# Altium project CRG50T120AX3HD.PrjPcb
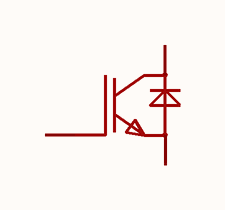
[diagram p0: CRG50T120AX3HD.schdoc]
1 sheet, 1 parts. Net scope: global (net labels, ports and power ports of the same name join across sheets).

## Sheet CRG50T120AX3HD.schdoc
size 127 x 101 mm

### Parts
Q?  crg50t120ax3hd  [TO-247-3_L15.9-W5.1-P5.44-L]  (value not drawn)

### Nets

Not connected (* = marked no-connect by the designer): Q? 1(G) 2(C) 3(E)

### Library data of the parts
Q? = crg50t120ax3hd: IGBT类型:-;耗散功率(Pd):682W;集射极击穿电压(Vces):1.2kV;集电极电流(Ic):50A;; Manufacturer: CRMICRO(华润微); AddInBom: yes; ModelId: 07f4db851a8c48cfb1c430cb719de897; ModelName: TO-247_3PIN-L15.9-W5.1-H25.0-P5.44-L; ModelTransform: 625.983,200.82637,0,0,0,0,0,5.905,-196.85; Pd - Power Dissipation: 682W; Collector-Emitter Breakdown Voltage (Vces): 1.2kV; Current - Collector(Ic): 50A; Current - Collector Pulsed (Icm): 200A; Collector Cut-Off Current (Ices): 1mA; Vce Saturation(VCE(sat)): 1.92V; Gate-Emitter Threshold Voltage (Vge(th)@Ic): 5.7V; Gate Charge(Qg): 253nC@15V; Input Capacitance(Cies): 7.852nF; Output Capacitance(Coes): 225pF; Reverse Transfer Capacitance (Cres): 111pF; Td(on): 101ns；89ns; Td(off): 349ns；370ns; Turn-On Energy (Eon): 3.8mJ；4.1mJ; Switching Energy(Eoff): 1.96mJ；2.5mJ; Reverse Recovery Time(trr): 86ns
